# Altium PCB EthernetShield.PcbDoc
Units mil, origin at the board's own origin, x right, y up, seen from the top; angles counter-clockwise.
Board outline 1375 x 745 mil, 2 copper layers (Top Layer, Bottom Layer); 7 components, 12 nets, 38 pads, 16 vias.
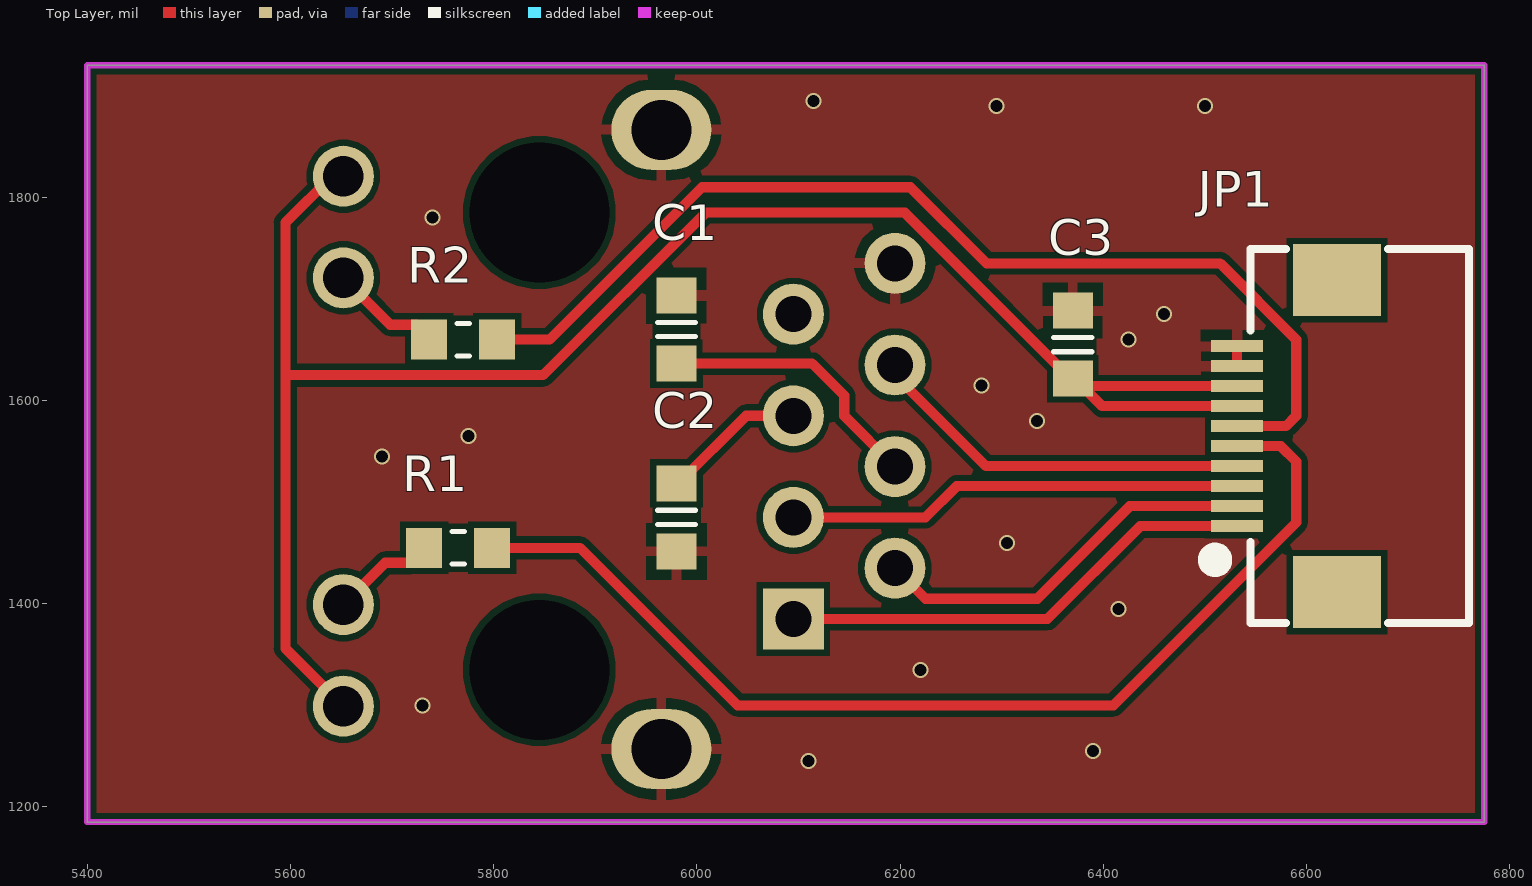
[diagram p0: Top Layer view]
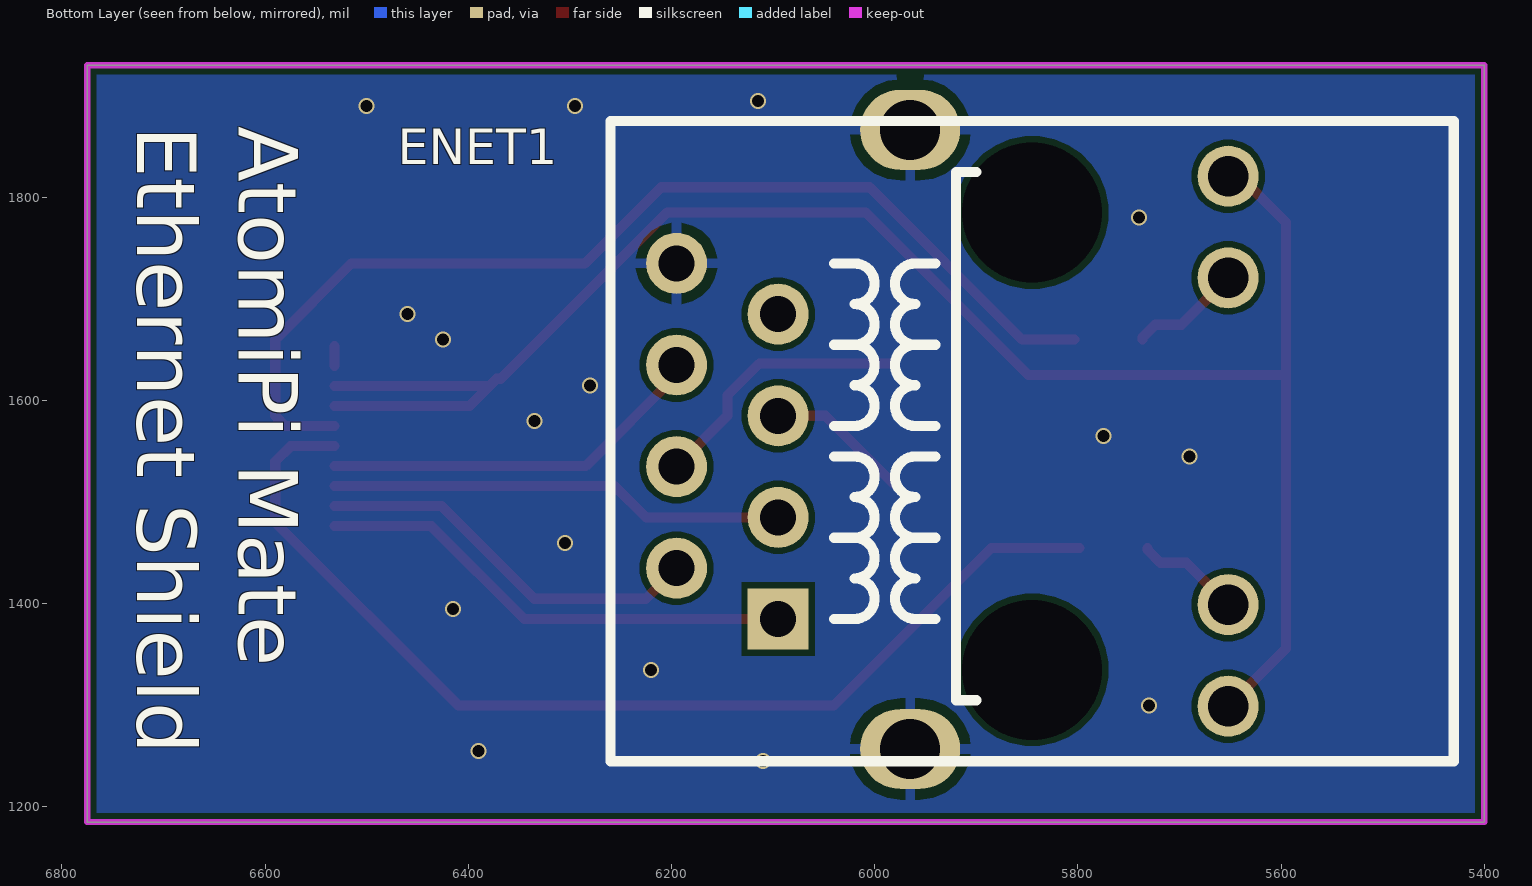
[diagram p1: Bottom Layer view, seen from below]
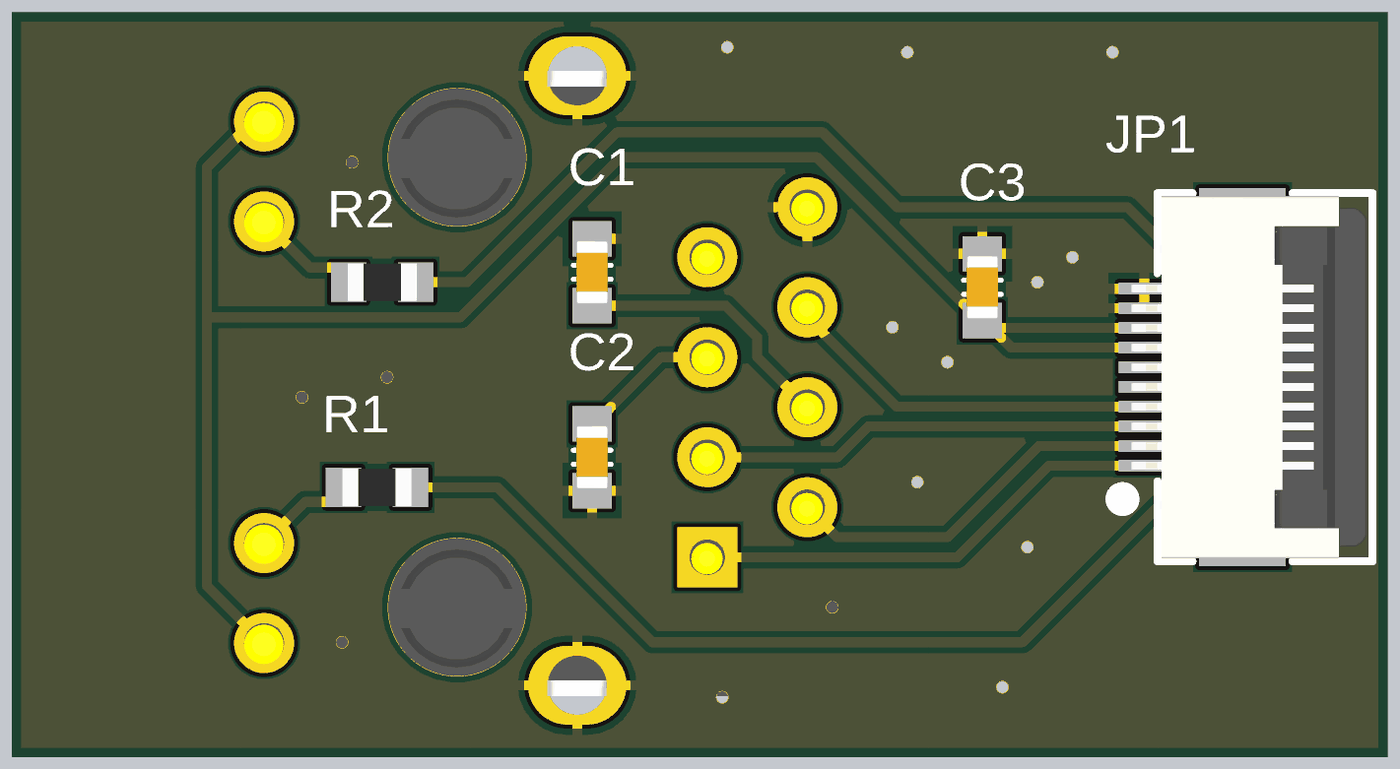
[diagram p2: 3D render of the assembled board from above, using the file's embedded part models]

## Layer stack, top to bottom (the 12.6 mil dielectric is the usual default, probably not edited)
Top Solder: solder mask 0.4, Solder Resist, Dk 3.5
Top Layer: signal copper 1.4
Dielectric 1: dielectric 12.6, FR-4, Dk 4.8
Bottom Layer: signal copper 1.4
Bottom Solder: solder mask 0.4, Solder Resist, Dk 3.5

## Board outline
5400,1185 6775,1185 6775,1930 5400,1930

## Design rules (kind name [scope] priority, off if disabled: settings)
Clearance [All] p1: gap=6 ignorepadtopadclearanceinfootprint=FALSE
PolygonConnect [All] p1: connectstyle=Relief reliefconductorwidth=10 reliefentries=4 polygonreliefangle="90 Angle" airgapwidth=10
RoutingVias [All] p1: holewidth=28 width=50 viastyle="Through Hole" minholewidth=28 minwidth=50 maxholewidth=28 maxwidth=50
SolderMaskExpansion [All] p1: expansion=4 istentingtop=FALSE
Width [All] p1: maxlimit=10 minlimit=10 preferedwidth=10
30 further rules are at their usual default settings.

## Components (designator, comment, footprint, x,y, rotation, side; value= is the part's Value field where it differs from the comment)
C1 "104" 0603-C 5980,1670 r270 top
C2 "104" 0603-C 5980,1485 r90 top
C3 "104" 0603-C 6370,1655 r270 top
ENET1 "HR911105A" RJ-45A12 5652.09,1299.17 r180 bottom
JP1 "FPC1.0-10P" "FPC0.5 2H-WS-10P" 6630,1565 r90 top
R1 "22R" 0603-R 5765,1455 r0 top
R2 "22R" 0603-R 5770,1660 r0 top

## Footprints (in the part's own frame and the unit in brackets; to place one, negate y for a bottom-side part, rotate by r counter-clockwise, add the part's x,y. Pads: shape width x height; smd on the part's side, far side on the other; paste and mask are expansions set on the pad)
0603-C [mm]
  rect 0.9x1 smd: 1(-0.85,0) 2(0.85,0)
  Top Layer pour cut-out: -0.4,0.6 0.4,0.6 0.4,-0.6 -0.4,-0.6
  silkscreen extent -0.18,-0.48 0.18,0.48, body extent -0.8,-0.4 0.8,0.4, height 0.8
0603-R [mm]
  rect 0.9x1 smd: 1(-0.85,0) 2(0.85,0)
  Top Layer pour cut-out: -0.4,0.6 0.4,0.6 0.4,-0.6 -0.4,-0.6
  silkscreen extent -0.15,-0.41 0.15,0.41, body extent -0.87,-0.47 0.88,0.48, height 0.54
"FPC0.5 2H-WS-10P" [mm] "长：9.2mm，宽：5.2mm，高：2mm"
  rect 1.8x2.2 smd: 0(-3.9,0) 0(3.9,0)
  rect 0.3x1.3 smd: 1(-2.25,2.497) 2(-1.75,2.497) 3(-1.25,2.497) 4(-0.75,2.497) 5(-0.25,2.497) 6(0.25,2.497) 7(0.75,2.497) 8(1.25,2.497) 9(1.75,2.497) 10(2.25,2.497)
  silkscreen extent -4.67,-3.3 4.67,3.23, body extent -4.6,-3.15 4.6,2.85, height 2
RJ-45A12 [mil]
  round 130 hole 137.8: 0(-192.91,35.83) 0(-192.91,485.83)
  rect 60x60 hole 35.43: 1(-442.91,85.83)
  round 60 hole 35.43: 2(-542.91,135.83) 3(-442.91,185.83) 4(-542.91,235.83) 5(-442.91,285.83) 6(-542.91,335.83) 7(-442.91,385.83) 8(-542.91,435.83)
  round 60 hole 40: 9(0,0) 10(0,100) 11(0,421.65) 12(0,521.65)
  oval 98.43x78.74 hole 59.06: 13(-312.99,-42.13) 14(-312.99,567.32)
  silkscreen extent -608,-54 222,576, body extent -605,-53 237,572, height 59

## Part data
C1 C2 C3: library part CAP, "陶瓷电容"
ENET1: "带灯以太网接口"
JP1: library part FPC_10P, "FPC连接器"
R1 R2: library part RES, "0603_R"

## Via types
v1: diameter 15.75, hole 11.81, Top Layer to Bottom Layer, tented both sides, 16 vias

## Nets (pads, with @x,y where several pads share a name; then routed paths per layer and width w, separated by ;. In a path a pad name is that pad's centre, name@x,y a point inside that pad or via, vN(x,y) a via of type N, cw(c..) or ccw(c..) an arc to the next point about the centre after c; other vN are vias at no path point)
3V3: C3.2 ENET1.9 ENET1.12 JP1.7 JP1.8 | length 1809.8
  Top Layer w10: ENET1.9 5595,1356.26 5595,1625 ; ENET1.12 5640.82,1820.82 5595,1775 5595,1625 ; JP1.7 6398.98,1594.53 C3.2@6379.29,1614.21 ; JP1.8 C3.2@6379.29,1614.21 ; 5595,1625 5848.58,1625 6008.58,1785 6204.57,1785 6368.03,1621.54 C3.2 6371.97,1621.54 C3.2@6379.29,1614.21
EPHY-LINK-LED: JP1.6 R2.2 | length 1048.3
  Top Layer w10: R2.2 5855,1660 6005,1810 6210,1810 6285,1735 6515,1735 6590,1660 6590,1585 6579.84,1574.84 JP1.6
EPHY-RXN: ENET1.6 JP1.4 | length 383.8
  Top Layer w10: ENET1.6 6195,1625 6284.53,1535.47 JP1.4
EPHY-RXP: ENET1.3 JP1.3 | length 449.4
  Top Layer w10: ENET1.3 6225,1485 6255.79,1515.79 JP1.3
EPHY-SPD-LED: JP1.5 R1.2 | length 1054.9
  Top Layer w10: R1.2 5885,1455 6040,1300 6410,1300 6590,1480 6590,1540 6574.84,1555.16 JP1.5
EPHY-TXN: ENET1.2 JP1.2 | length 386.9
  Top Layer w10: ENET1.2 6225,1405 6335,1405 6426.1,1496.1 JP1.2
EPHY-TXP: ENET1.1 JP1.1 | length 474.6
  Top Layer w10: ENET1.1 6345,1385 6436.42,1476.42 JP1.1
GND: C1.1 C2.1 C3.1 ENET1.8 ENET1.13 ENET1.14 JP1.9 JP1.10 | length 19.7
  Top Layer w10: JP1.9 JP1.10
  other v1: 6110,1245 6390,1255 5730,1300 6220,1335 6415,1395 6305,1460 5690,1545 5775,1565 6335,1580 6280,1615 6425,1660 6460,1685 5740,1780 6295,1890 6500,1890 6115,1895
NetC1_2: C1.2 ENET1.4 | length 268.8
  Top Layer w10: C1.2 6113.46,1636.54 6145,1605 6145,1585 ENET1.4
NetC2_2: C2.2 ENET1.5 | length 142.6
  Top Layer w10: C2.2 5981.97,1518.46 6048.5,1585 ENET1.5
NetENET1_10: ENET1.10 R1.1 | length 103.7
  Top Layer w10: ENET1.10 5693.23,1440.31 5718.82,1440.31 5731.54,1453.03 R1.1
NetENET1_11: ENET1.11 R2.1 | length 110.8
  Top Layer w10: ENET1.11 5698.22,1674.69 5723.82,1674.69 5736.54,1661.97 R2.1
pads on no net: ENET1.0 ENET1.7 JP1.0

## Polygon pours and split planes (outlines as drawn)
GND on Top Layer "GND_L01_P000" (solid, pour order 0): 6775,1930 5400,1930 5400,1185 6775,1185
GND on Bottom Layer "GND_L02_P001" (solid, pour order 1): 6775,1930 5400,1930 5400,1185 6775,1185

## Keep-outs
Keep-Out Layer:
  the board outline again, w6

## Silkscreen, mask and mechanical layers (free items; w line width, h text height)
Bottom Overlay:
  text "AtomiPi Mate / Ethernet Shield" at 6745,1870 h100 r90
